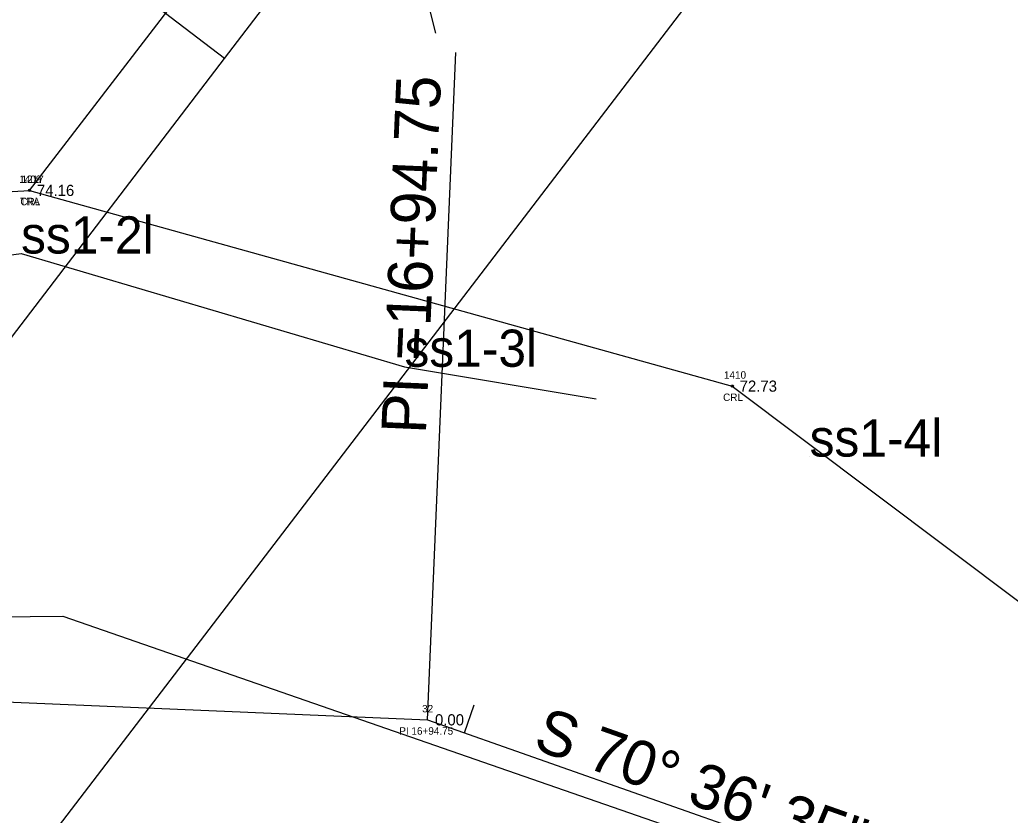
# Model space of a CAD drawing. Extents: x 2500794 to 2511032, y 910653 to 917533.
# Drawn here: x 2506204.2 to 2506337.4, y 913842.2 to 913949.2 of the extents above; entities that cross this region are included whole.
import ezdxf

# ---------------------------------------------------------------- set-up
doc = ezdxf.new("R2010")
doc.units = 0
for name, color, linetype in [('Default', 7, 'Continuous'), ('RD_EX_DV_Prop', 7, 'Continuous'), ('RD_EX_H2O', 7, 'Continuous'), ('RD_EX_H2O_txCode', 7, 'Continuous'), ('RD_EX_RW', 7, 'Continuous'), ('RD_EX_TX_H2O_ELEV', 7, 'Continuous'), ('RD_EX_TX_VEG_ELEV', 7, 'Continuous'), ('RD_EX_VEG', 7, 'Continuous'), ('RD_EX_VEG_txCode', 7, 'Continuous'), ('RD_HC_Cl', 7, 'Continuous'), ('RD_HC_Data', 7, 'Continuous'), ('RD_HC_Data_Tic', 7, 'Continuous'), ('RD_HC_Survey_ELEV', 7, 'Continuous'), ('RD_HC_txCode', 7, 'Continuous'), ('RD_PD_RW', 7, 'Continuous'), ('RD_Sketch9', 7, 'Continuous'), ('RD_SMD_Locator', 7, 'Continuous')]:
    doc.layers.add(name, color=color, linetype=linetype)

# ---------------------------------------------------------------- blocks, each defined once
blk = doc.blocks.new('POINT_DISPLAY')
at = {"layer": 'Default'}
blk.add_line((0, 0), (0, 0), dxfattribs=at)
blk = doc.blocks.new('Non-Wetland Waters (Tributaries)')
at = {"layer": 'Default'}
blk.add_lwpolyline([(636556.303, 232132.46), (636575.915, 232135.121), (636589.015, 232131.251), (636595.56, 232130.161)], dxfattribs=at)

msp = doc.modelspace()

# ---------------------------------------------------------------- linework, layer by layer
at = {"layer": 'RD_EX_DV_Prop'}
for p, q in [((2506174.02, 913868.65), (2506210, 913869)), ((2506210, 913869), (2506334, 913826))]:
    msp.add_line(p, q, dxfattribs=at)
at = {"layer": 'RD_EX_H2O_txCode'}
msp.add_lwpolyline([(2505808.2, 913925.07), (2505825.64, 913915.36), (2505914.54, 913915.98), (2505996.26, 913926.38), (2506005.4, 913936.74), (2506012.64, 913937.08), (2506022.61, 913935.73), (2506047.54, 913912.75), (2506069, 913926.42), (2506101.76, 913929.76), (2506134.82, 913911.49), (2506168.31, 913924.14), (2506205.52, 913926.29), (2506300.04, 913899.96), (2506387.24, 913834.45), (2506403.62, 913708.7), (2506351.33, 913635.45), (2506287.73, 913577.34)], dxfattribs=at)
at = {"layer": 'RD_EX_RW'}
for p, q in [((2506231.75, 913944.02), (2506198.38, 913969.53)), ((2506073.83, 913737.47), (2506231.75, 913944.02))]:
    msp.add_line(p, q, dxfattribs=at)
at = {"layer": 'RD_EX_VEG'}
msp.add_line((2506205.52, 913926.29), (2506806.36, 914708.13), dxfattribs=at)
at = {"layer": 'RD_HC_Cl'}
for p, q in [((2505870.76, 913871.61), (2506259.06, 913855.07)), ((2506259.06, 913855.07), (2506342.51, 913825.7))]:
    msp.add_line(p, q, dxfattribs=at)
at = {"layer": 'RD_HC_Data'}
for p, q in [((2506230.5, 914065.87), (2506260.14, 913947.45)), ((2506259.06, 913855.07), (2506262.88, 913944.83))]:
    msp.add_line(p, q, dxfattribs=at)
at = {"layer": 'RD_HC_Data_Tic'}
msp.add_line((2506264.01, 913853.33), (2506265.34, 913857.1), dxfattribs=at)
at = {"layer": 'RD_PD_RW'}
msp.add_line((2506231.75, 913944.02), (2506249.97, 913967.86), dxfattribs=at)
at = {"layer": 'RD_Sketch9'}
msp.add_line((2505975.42, 913534.66), (2506308.52, 913970.35), dxfattribs=at)
at = {"layer": 'RD_SMD_Locator'}
for centre in [(2506205.52, 913926.29), (2506205.52, 913926.29), (2506300.04, 913899.96)]:
    msp.add_circle(centre, 0.15, dxfattribs=at)

# ---------------------------------------------------------------- block references
at = {"layer": 'Default', "xscale": 3.937007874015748, "yscale": 3.937007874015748}
for name, p in [('Non-Wetland Waters (Tributaries)', (0, 0)), ('POINT_DISPLAY', (2506204.39, 913917.8)), ('POINT_DISPLAY', (2506204.39, 913917.8)), ('POINT_DISPLAY', (2506255.96, 913902.56)), ('POINT_DISPLAY', (2506255.96, 913902.56)), ('POINT_DISPLAY', (2506310.45, 913890.48)), ('POINT_DISPLAY', (2506310.45, 913890.48))]:
    msp.add_blockref(name, p, dxfattribs=at)
at = {"layer": 'RD_EX_H2O', "xscale": 3.937007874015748, "yscale": 3.937007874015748}
msp.add_blockref('Non-Wetland Waters (Tributaries)', (0, 0), dxfattribs=at)

# ---------------------------------------------------------------- texts
at = {"layer": 'Default'}
for s, p in [('ss1-2l', (2506204.39, 913917.8)), ('ss1-2l', (2506204.39, 913917.8)), ('ss1-3l', (2506255.96, 913902.56)), ('ss1-3l', (2506255.96, 913902.56)), ('ss1-4l', (2506310.45, 913890.48)), ('ss1-4l', (2506310.45, 913890.48))]:
    msp.add_text(s, height=5, dxfattribs=at).set_placement(p)
at = {"layer": 'RD_EX_H2O_txCode'}
for s, p in [('1409', (2506204.14, 913927.29)), ('CRL', (2506204.29, 913924.29)), ('1410', (2506298.93, 913900.96)), ('CRL', (2506298.81, 913897.96))]:
    msp.add_text(s, height=1, dxfattribs=at).set_placement(p)
at = {"layer": 'RD_EX_TX_H2O_ELEV'}
for s, p in [('74.16', (2506206.52, 913925.54)), ('72.73', (2506301.04, 913899.21))]:
    msp.add_text(s, height=1.5, dxfattribs=at).set_placement(p)
at = {"layer": 'RD_EX_TX_VEG_ELEV'}
msp.add_text('74.16', height=1.5, dxfattribs=at).set_placement((2506206.52, 913925.54))
at = {"layer": 'RD_EX_VEG_txCode'}
for s, p in [('1217', (2506204.46, 913927.29)), ('TRA', (2506204.24, 913924.29))]:
    msp.add_text(s, height=1, dxfattribs=at).set_placement(p)
at = {"layer": 'RD_HC_Data'}
for s, rotation, p in [('PI =16+94.75', 87.5616, (2506258.83, 913893.47)), ('S 70%%d 36\' 35" E', 340.6098, (2506273.07, 913851.2))]:
    msp.add_text(s, height=6, rotation=rotation, dxfattribs=at).set_placement(p)
at = {"layer": 'RD_HC_Survey_ELEV'}
msp.add_text('0.00', height=1.5, dxfattribs=at).set_placement((2506260.06, 913854.32))
at = {"layer": 'RD_HC_txCode'}
for s, p in [('32', (2506258.33, 913856.07)), ('PI 16+94.75', (2506255.26, 913853.07))]:
    msp.add_text(s, height=1, dxfattribs=at).set_placement(p)

doc.saveas('drawing.dxf')
